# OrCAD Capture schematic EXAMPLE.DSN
size A; company: OrCAD; note: Example
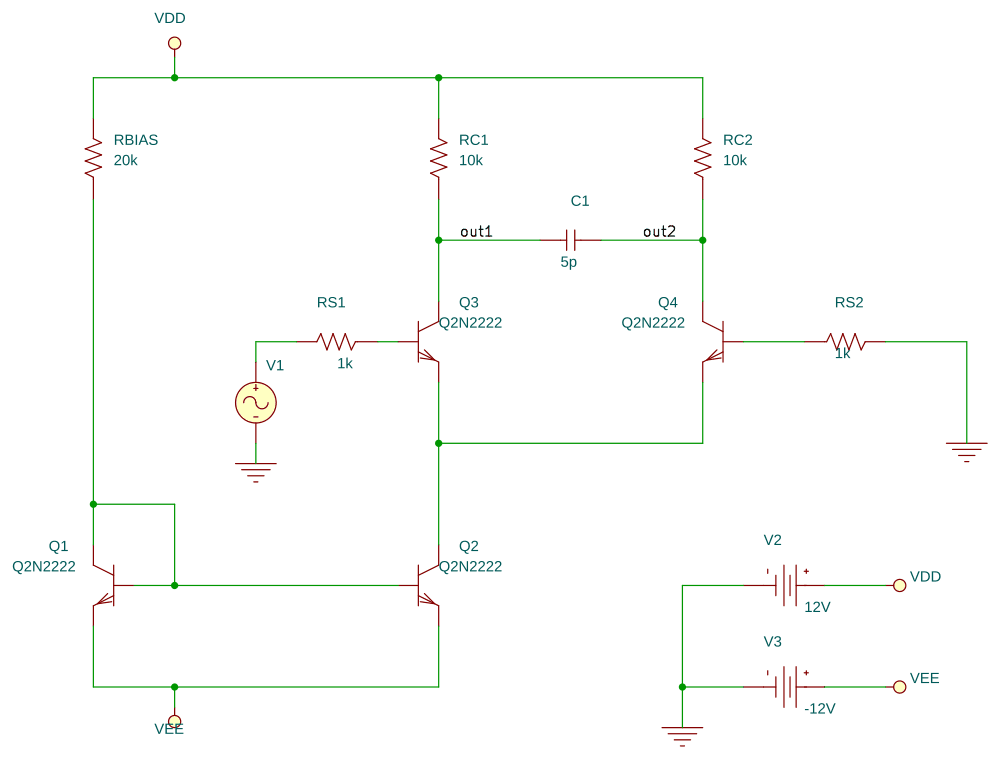
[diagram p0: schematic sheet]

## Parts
C1  5p  [CK05]
Q1  Q2N2222  [TO18]
Q2  Q2N2222  [TO18]
Q3  Q2N2222  [TO18]
Q4  Q2N2222  [TO18]
RBIAS  20k  [RC05]
RC1  10k  [RC05]
RC2  10k  [RC05]
RS1  1k  [RC05]
RS2  1k  [RC05]
V1  VSIN
V2  VDC
V3  VDC

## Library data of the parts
C1 = C
Q1-Q4 = Q2N2222
RBIAS RC1 RC2 RS1 RS2 = R
V1 = VSIN: AC: 1; FREQ: 5MEG; VAMPL: 0.1V; VOFF: 0
V2 = VDC: DC: 12V
V3 = VDC: DC: -12V

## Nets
VDD: RBIAS.2 RC1.2 RC2.2 V2.0(+)
VEE: Q1.1(e) Q2.1(e) V3.0(+)
0: RS2.2 V1.2(-) V2.1(-) V3.1(-)
out1: C1.1 Q3.3(c) RC1.1
out2: C1.2 Q4.3(c) RC2.1
N00061: Q3.2(b) RS1.1
N00078: Q1.2(b) Q1.3(c) Q2.2(b) RBIAS.1
N00112: Q4.2(b) RS2.1
N00240: RS1.2 V1.1(+)
N00315: Q2.3(c) Q3.1(e) Q4.1(e)
